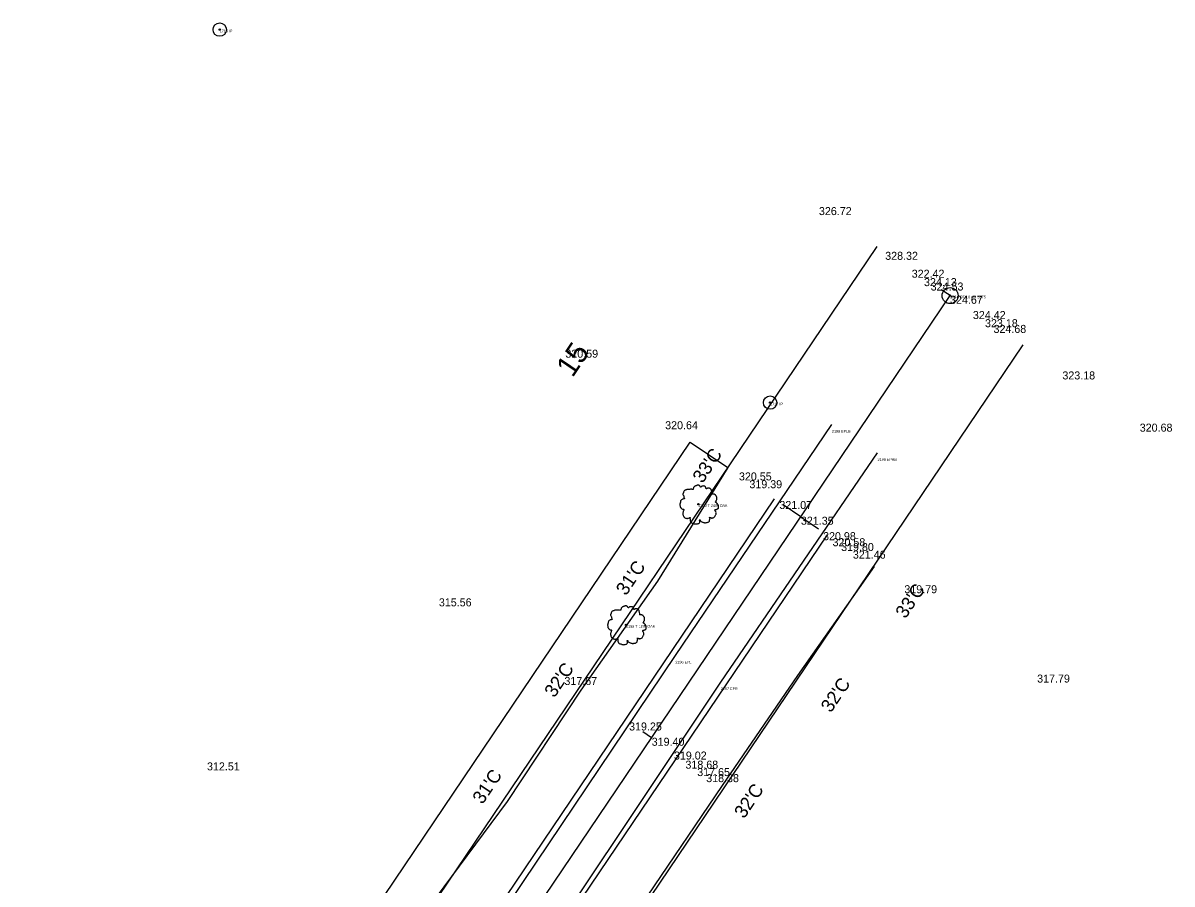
# Model space of a CAD drawing. Extents: x 49683 to 58852, y 49525 to 54803.
# Drawn here: x 56915.8 to 57346.5, y 54339.7 to 54662.5 of the extents above; entities that cross this region are included whole.
import ezdxf

# ---------------------------------------------------------------- set-up
doc = ezdxf.new("R2010")
doc.units = 0
for name, color, linetype in [('Level 1', 7, 'Continuous'), ('Level 11', 7, 'Continuous'), ('Level 12', 7, 'Continuous'), ('Level 18', 7, 'Continuous'), ('Level 20', 7, 'Continuous'), ('Level 21', 7, 'Continuous'), ('Level 3', 7, 'Continuous'), ('Level 32', 7, 'Continuous'), ('Level 33', 7, 'Continuous'), ('Level 48', 7, 'Continuous'), ('Level 51', 7, 'Continuous'), ('Level 53', 7, 'Continuous'), ('Level 61', 7, 'Continuous'), ('Level 62', 7, 'Continuous')]:
    doc.layers.add(name, color=color, linetype=linetype)

# ---------------------------------------------------------------- blocks, each defined once
blk = doc.blocks.new('PC')
at = {"layer": 'Level 1'}
for radius in [3, 0.282]:
    blk.add_circle((0, 0), radius, dxfattribs=at)
blk = doc.blocks.new('IP')
at = {"layer": 'Level 12'}
for radius in [2.5, 0.25]:
    blk.add_circle((0, 0), radius, dxfattribs=at)
blk = doc.blocks.new('T1')
at = {"layer": 'Level 11'}
for centre, radius in [((0, 0), 0.25), ((-0.01, -0.02), 0.0001)]:
    blk.add_circle(centre, radius, dxfattribs=at)
for points in [[(0.13, 7.17), (-0.17, 7.19), (-0.49, 7.09), (-0.74, 6.99), (-0.97, 6.92), (-1.19, 6.82), (-1.49, 6.64), (-1.72, 6.44), (-1.84, 6.19), (-1.89, 5.97), (-1.94, 5.69), (-1.94, 5.52), (-2.07, 5.49), (-2.22, 5.52), (-2.47, 5.59), (-2.72, 5.59), (-2.97, 5.59), (-3.32, 5.57), (-3.67, 5.57), (-3.94, 5.52), (-4.27, 5.47), (-4.64, 5.34), (-4.99, 5.22), (-5.29, 4.97), (-5.54, 4.49), (-5.67, 4.14), (-5.82, 3.89), (-5.67, 3.44), (-5.49, 3.09), (-5.47, 2.89), (-5.39, 2.47), (-5.29, 2.24), (-5.17, 2.04), (-5.24, 2.02), (-5.62, 1.97), (-5.92, 1.87), (-6.34, 1.64), (-6.57, 1.42), (-6.67, 1.09), (-6.69, 0.75), (-6.79, 0.55), (-6.87, 0.27), (-6.89, 0.2), (-6.94, -0.13), (-6.84, -0.58), (-6.82, -0.93), (-6.69, -1.15), (-6.54, -1.33), (-6.37, -1.58), (-5.97, -1.8), (-5.64, -1.9), (-5.44, -1.93), (-5.62, -2.43), (-5.67, -2.78), (-5.79, -3.18), (-5.79, -3.25), (-5.84, -3.73), (-5.69, -4.05), (-5.62, -4.43), (-5.44, -4.65), (-5.17, -4.95), (-4.84, -5.18), (-4.34, -5.3), (-3.94, -5.28), (-3.37, -5.1), (-3.12, -5.03), (-3.14, -5.2), (-3.12, -5.58), (-3.12, -6), (-2.97, -6.33), (-2.87, -6.6), (-2.72, -6.85), (-2.39, -7.08), (-1.99, -7.15), (-1.57, -7.3), (-1.12, -7.38), (-0.62, -7.4), (-0.02, -7.25), (0.26, -7.13), (0.36, -6.95), (0.56, -6.58), (0.51, -6.35), (0.53, -5.75), (0.63, -5.93), (0.81, -6.28), (1.31, -6.58), (1.71, -6.75), (2.18, -6.9), (2.48, -6.98), (2.96, -6.9), (3.33, -6.83), (3.71, -6.7), (4.01, -6.43), (4.18, -6.15), (4.23, -5.88), (4.31, -5.5), (4.36, -5.33)], [(4.36, -5.33), (4.28, -5.15), (4.23, -4.9), (4.31, -4.93), (4.48, -4.98), (4.75, -5.1), (4.98, -5.18), (5.3, -5.15), (5.58, -5.05), (6.03, -4.78), (6.3, -4.3), (6.58, -3.9), (6.65, -3.58), (6.6, -3.35), (6.58, -2.85), (6.38, -2.6), (6.33, -2.48), (6.23, -2.08), (6.3, -2.03), (6.58, -1.98), (6.95, -1.85), (7.23, -1.73), (7.45, -1.55), (7.53, -1.33), (7.5, -0.93), (7.55, -0.53), (7.48, -0.38), (7.38, -0.23), (7.3, -0.03), (7.15, 0.12), (7.05, 0.27), (6.95, 0.37), (6.83, 0.52), (6.65, 0.65), (6.5, 0.7), (6.45, 0.85), (6.6, 1.04), (6.65, 1.14), (6.68, 1.37), (6.9, 1.72), (6.95, 2.12), (6.9, 2.54), (6.85, 2.82), (6.7, 3.09), (6.5, 3.34), (6.38, 3.52), (6.2, 3.64), (5.88, 3.77), (5.63, 3.82), (5.28, 3.82), (5.08, 3.87), (5.1, 3.92), (5.1, 4.07), (5.1, 4.34), (5.03, 4.79), (4.88, 5.29), (4.88, 5.32), (4.78, 5.57), (4.56, 5.77), (4.38, 5.87), (4.18, 5.99), (3.93, 6.02), (3.63, 6.02), (3.36, 5.97), (3.16, 5.87), (2.98, 5.74), (2.91, 5.89), (2.81, 6.19), (2.76, 6.34), (2.61, 6.52), (2.38, 6.72), (1.93, 6.84), (1.31, 6.77), (1.01, 6.57), (0.86, 6.39), (0.81, 6.52), (0.61, 6.72), (0.51, 6.89), (0.33, 7.02), (0.18, 7.12), (0.08, 7.17)]]:
    blk.add_spline(points, degree=3, dxfattribs=at)

msp = doc.modelspace()

# ---------------------------------------------------------------- linework, layer by layer
at = {"layer": 'Level 1'}
for p, q in [((57263.35, 54560.26), (57260.04, 54562.5)), ((56927.66, 54062.96), (57263.35, 54560.26)), ((57207.4, 54477.37), (57200.77, 54481.85)), ((57207.4, 54477.37), (57214.03, 54472.9)), ((57151.45, 54394.49), (57148.14, 54396.73))]:
    msp.add_line(p, q, dxfattribs=at)
at = {"layer": 'Level 12'}
for p, q in [((56939.44, 54139.39), (57236, 54578.72)), ((57083.33, 54234.58), (57290.7, 54541.79))]:
    msp.add_line(p, q, dxfattribs=at)
at = {"layer": 'Level 18'}
for p, q in [((57153.81, 54453.23), (57180.14, 54495.78)), ((57206.27, 54417.82), (57234.99, 54458.75)), ((57125.02, 54412.34), (57153.81, 54453.23)), ((57177.98, 54376.59), (57206.27, 54417.82)), ((57097.37, 54370.67), (57125.02, 54412.34)), ((57149.97, 54335.17), (57177.98, 54376.59)), ((57067.58, 54330.45), (57097.37, 54370.67))]:
    msp.add_line(p, q, dxfattribs=at)
at = {"layer": 'Level 20'}
for p, q in [((56938.73, 54100.8), (57197.46, 54484.09)), ((56994.8, 54140.97), (57217.35, 54470.66))]:
    msp.add_line(p, q, dxfattribs=at)
at = {"layer": 'Level 3'}
for p, q in [((57160.36, 54425.36), (57219.04, 54511.9)), ((57177.41, 54415.43), (57236.17, 54501.33)), ((57103.39, 54340.7), (57160.36, 54425.36)), ((57118.64, 54327.36), (57177.41, 54415.43)), ((57057.7, 54272.01), (57103.39, 54340.7))]:
    msp.add_line(p, q, dxfattribs=at)
at = {"layer": 'Level 33'}
for p, q in [((56915.8, 54134.76), (57165.96, 54505.35)), ((57165.96, 54505.35), (57180.05, 54495.84))]:
    msp.add_line(p, q, dxfattribs=at)

# ---------------------------------------------------------------- block references
at = {"layer": 'Level 1'}
msp.add_blockref('PC', (57263.35, 54560.26), dxfattribs=at)
at = {"layer": 'Level 11'}
for p in [(57168.98, 54482.07), (57141.88, 54436.83)]:
    msp.add_blockref('T1', p, dxfattribs=at)
at = {"layer": 'Level 12'}
for p in [(56989.54, 54659.97), (57195.87, 54520.15)]:
    msp.add_blockref('IP', p, dxfattribs=at)

# ---------------------------------------------------------------- texts
at = {"layer": 'Level 21'}
msp.add_text('15', height=8, rotation=55.9793, dxfattribs=at).set_placement((57121.79, 54529.27))
at = {"layer": 'Level 32'}
for s, p in [('326.72', (57214.17, 54590.46)), ('328.32', (57239.01, 54573.69)), ('322.42', (57248.95, 54566.98)), ('324.13', (57253.56, 54563.83)), ('324.53', (57256.06, 54562.18)), ('324.67', (57263.32, 54557.2)), ('324.42', (57271.89, 54551.49)), ('323.18', (57276.43, 54548.43)), ('324.68', (57279.6, 54546.29)), ('320.59', (57119.12, 54537)), ('323.18', (57305.43, 54528.85)), ('320.64', (57156.53, 54510.18)), ('320.68', (57334.43, 54509.28)), ('320.55', (57184.19, 54491)), ('319.39', (57188.11, 54488.07)), ('321.07', (57199.33, 54480.29)), ('321.35', (57207.41, 54474.39)), ('320.98', (57215.72, 54468.6)), ('320.58', (57219.28, 54466.33)), ('319.80', (57222.48, 54464.53)), ('321.46', (57226.9, 54461.68)), ('319.79', (57246.19, 54448.71)), ('315.56', (57071.7, 54443.79)), ('317.67', (57118.76, 54414.31)), ('317.79', (57295.97, 54415.22)), ('319.25', (57143, 54397.26)), ('319.40', (57151.48, 54391.54)), ('319.02', (57159.82, 54386.37)), ('312.51', (56984.78, 54382.3)), ('318.68', (57164.13, 54382.95)), ('317.65', (57168.55, 54380.17)), ('318.38', (57171.91, 54377.9))]:
    msp.add_text(s, height=3, dxfattribs=at).set_placement(p)
at = {"layer": 'Level 48'}
for s, p in [("33'C", (57170.56, 54489.65)), ("31'C", (57141.84, 54447.53)), ("33'C", (57246.6, 54438.9)), ("32'C", (57115.01, 54409.27)), ("32'C", (57218.64, 54403.65)), ("31'C", (57088.06, 54369.31)), ("32'C", (57186.16, 54363.95))]:
    msp.add_text(s, height=5, rotation=55.9793, dxfattribs=at).set_placement(p)
at = {"layer": 'Level 51'}
msp.add_text('186 POT 16+00 S575 ', height=1, dxfattribs=at).set_placement((57263.35, 54559.26))
at = {"layer": 'Level 53'}
for s, p in [('2199 EPLB ', (57219.04, 54508.9)), ('2198 EPRB ', (57236.17, 54498.33)), ('2196 EPL ', (57160.36, 54422.36)), ('2197 EPR ', (57177.41, 54412.43))]:
    msp.add_text(s, height=1, dxfattribs=at).set_placement(p)
at = {"layer": 'Level 61'}
for s, p in [('2200 T 24IN OAK ', (57168.98, 54481.07)), ('2195 T 12IN OAK ', (57141.88, 54435.83))]:
    msp.add_text(s, height=1, dxfattribs=at).set_placement(p)
at = {"layer": 'Level 62'}
for s, p in [('1719 IP ', (56989.54, 54658.97)), ('1717 IP ', (57195.87, 54519.15))]:
    msp.add_text(s, height=1, dxfattribs=at).set_placement(p)

doc.saveas('drawing.dxf')
